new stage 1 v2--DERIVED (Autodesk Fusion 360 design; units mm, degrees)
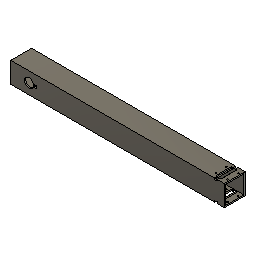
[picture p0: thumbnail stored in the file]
parameter "d495" = 0
parameter "d496" = 0
parameter "d497" = 0
parameter "d498" = 0
sketch "Sketch1" plane through (0, 0, 0) normal (1, 0, 0) x axis (0, 0, -1)
  line L1 (50.8, 0) -> (0, 0)
  line L2 (50.8, 50.8) -> (50.8, 0)
  line L3 (0, 50.8) -> (50.8, 50.8)
  line L4 (0, 0) -> (0, 50.8)
  line L5 (47.5234, 3.2766) -> (3.2766, 3.2766)
  line L6 (47.5234, 47.5234) -> (47.5234, 3.2766)
  line L7 (3.2766, 47.5234) -> (47.5234, 47.5234)
  line L8 (3.2766, 3.2766) -> (3.2766, 47.5234)
  point P1 (0, 0)
  point P2 (0, 0)
  point P3 (50.8, 0)
  point P5 (0, 50.8)
  horizontal L1
  vertical L2
  horizontal L3
  vertical L4
  coincident P1 P2
  dimension "d1_1" distance P2 P3 = 50.8
  dimension "d2_1" distance P2 P5 = 50.8
  dimension "d3_1" = -3.2766
  dimension "d158" OffsetX = 0
  dimension "d159" OffsetY = 0
  dimension "d160" OffsetZ = 0
  dimension "d161" AngleZ = 0
  dimension "d215" OffsetX = 0
  dimension "d216" OffsetY = 0
  dimension "d217" OffsetZ = 0
  dimension "d218" AngleZ = 0
  dimension "d223" OffsetX = 0
  dimension "d224" OffsetY = 0
  dimension "d225" OffsetZ = 0
  dimension "d226" AngleZ = 0
  dimension "d231" OffsetX = 0
  dimension "d232" OffsetY = 0
  dimension "d233" OffsetZ = 0
  dimension "d234" AngleZ = 0
  dimension "d239" OffsetX = 0
  dimension "d240" OffsetY = 0
  dimension "d241" OffsetZ = 0
  dimension "d242" AngleZ = 0
  dimension "d339" OffsetX = 0
  dimension "d340" OffsetY = 0
  dimension "d341" OffsetZ = 0
  dimension "d342" AngleZ = 0
  dimension "d347" OffsetX = 0
  dimension "d348" OffsetY = 0
  dimension "d349" OffsetZ = 0
  dimension "d350" AngleZ = 0
  dimension "d355" OffsetX = 0
  dimension "d356" OffsetY = 0
  dimension "d357" OffsetZ = 0
  dimension "d358" AngleZ = 0
  dimension "d363" OffsetX = 0
  dimension "d364" OffsetY = 0
  dimension "d365" OffsetZ = 0
  dimension "d366" AngleZ = 0
  dimension "d376" OffsetX = 0
  dimension "d377" OffsetY = 0
  dimension "d378" OffsetZ = 0
  dimension "d379" AngleZ = 0
  dimension "d384" OffsetX = 0
  dimension "d385" OffsetY = 0
  dimension "d386" OffsetZ = 0
  dimension "d387" AngleZ = 0
  dimension "d392" OffsetX = 0
  dimension "d393" OffsetY = 0
  dimension "d394" OffsetZ = 0
  dimension "d395" AngleZ = 0
  dimension "d479" OffsetX = 0
  dimension "d480" OffsetY = 0
  dimension "d481" OffsetZ = 0
  dimension "d482" AngleZ = 0
  dimension "d487" OffsetX = 0
  dimension "d488" OffsetY = 0
  dimension "d489" OffsetZ = 0
  dimension "d490" AngleZ = 0
extrude "Extrude1" new body sketch "Sketch1" along a picked direction blind 520.7 named "d4_1"
hole "Hole2" HoleDepth 101.6 HoleDiameter 22.225 TipAngle 118 RefDim1 44.45 (= "1 in + ( 3 / 4 ) * 1 in") RefDim2 25.4
sketch "Sketch2" plane through (0, 0, 0) normal (0, 0, 1) x axis (1, 0, 0)
  line L1 (0, 50.8) -> (520.7, 50.8)
  line L2 (0, 0) -> (0, 50.8)
  line L3 (520.7, 0) -> (0, 0)
  line L4 (496.7478, 47.498) -> (503.3518, 47.498)
  line L5 (496.7478, 54.102) -> (496.7478, 47.498)
  line L6 (503.3518, 54.102) -> (496.7478, 54.102)
  line L7 (503.3518, 47.498) -> (503.3518, 54.102)
  line L8 (496.7478, 54.102) -> (503.3518, 47.498)
  line L9 (503.3518, 54.102) -> (496.7478, 47.498)
  line L10 (496.7478, 3.302) -> (503.3518, 3.302)
  line L11 (496.7478, -3.302) -> (496.7478, 3.302)
  line L12 (503.3518, -3.302) -> (496.7478, -3.302)
  line L13 (503.3518, 3.302) -> (503.3518, -3.302)
  line L14 (496.7478, -3.302) -> (503.3518, 3.302)
  line L15 (503.3518, -3.302) -> (496.7478, 3.302)
  line L16 (520.7, 50.8) -> (520.7, 0)
  line L17 (520.7, 50.8) -> (520.7, 0)
  circle C1 centre (44.45, 25.4) radius 11.1125
  circle C2 centre (500.0498, 50.8) radius 3.302
  circle C3 centre (500.0498, 0) radius 3.302
  point P7 (500.0498, 50.8)
  point P8 (500.0498, 0)
  point P13 (500.0498, 50.8)
  point P18 (500.0498, 0)
  point P10 (496.7478, 47.498)
  point P11 (496.7478, 54.102)
  point P12 (503.3518, 54.102)
  point P16 (496.7478, -3.302)
  point P17 (503.3518, -3.302)
  point P15 (496.7478, 3.302)
  coincident L1 P7
  coincident L3 P8
  perpendicular L4 L5
  parallel L4 L6
  parallel L5 L7
  horizontal L4
  coincident L8 P13
  coincident L9 P13
  coincident P7 P13
  perpendicular L10 L11
  parallel L10 L12
  parallel L11 L13
  horizontal L10
  coincident L14 P18
  coincident L15 P18
  coincident P8 P18
  dimension "d412" diameter C2 = 6.604
  dimension "d413" diameter C3 = 6.604
  dimension "d428" distance P10 P11 = 6.604
  dimension "d429" distance P11 P12 = 6.604
  dimension "d430" distance P16 P17 = 6.604
  dimension "d431" distance P15 P16 = 6.604
  dimension "d540" distance L13 L17 = 17.3482
  dimension "d541" distance L7 L17 = 17.3482
extrude "Extrude3" cut sketch "Sketch2" profile of L1 L3 C2 C3 L4 L5 L7 L10 L11 L13 along a picked direction blind -50.8
sketch "Sketch3" plane through (0, 0, 0) normal (0, -1, 0) x axis (1, 0, 0)
  line L1 (520.7, -50.8) -> (503.3518, -50.8)
  line L2 (503.3518, 0) -> (520.7, 0)
  line L3 (493.1918, -6.35) -> (506.9078, -6.35)
  line L4 (493.1918, -19.05) -> (493.1918, -6.35)
  line L5 (506.9078, -19.05) -> (493.1918, -19.05)
  line L6 (506.9078, -6.35) -> (506.9078, -19.05)
  line L7 (493.1918, -19.05) -> (506.9078, -19.05)
  line L8 (493.1918, -44.45) -> (493.1918, -19.05)
  line L9 (506.9078, -44.45) -> (493.1918, -44.45)
  line L10 (506.9078, -19.05) -> (506.9078, -44.45)
  line L11 (503.3518, -50.8) -> (503.3518, 0)
  line L12 (496.7478, 0) -> (496.7478, -50.8)
  line L13 (520.7, 0) -> (520.7, -50.8)
  line L14 (496.7478, 0) -> (496.7478, -50.8)
  line L15 (0, 0) -> (496.7478, 0)
  line L16 (0, -50.8) -> (0, 0)
  line L17 (496.7478, -50.8) -> (0, -50.8)
  point P6 (506.9078, -6.35)
  point P9 (506.9078, -19.05)
  point P7 (493.1918, -6.35)
  point P10 (506.9078, -19.05)
  point P11 (493.1918, -19.05)
  point P13 (506.9078, -44.45)
  horizontal L3
  vertical L4
  horizontal L5
  vertical L6
  horizontal L7
  vertical L8
  horizontal L9
  vertical L10
  dimension "d418" distance P6 P9 = 12.7
  dimension "d419" distance P6 P7 = 13.716
  dimension "d420" distance P10 P11 = 13.716
  dimension "d421" distance P10 P13 = 25.4
  dimension "d422" distance L1 L9 = 6.35
  dimension "d423" distance L2 L3 = 6.35
  dimension "d432" distance L4 L12 = 3.556
  dimension "d433" distance L8 L12 = 3.556
extrude "Extrude4" cut sketch "Sketch3" profile of L3 L4 L5 L6 L7 L8 L9 L10 L11 L12 against normal blind 3.175
extrude "Extrude5" sketch "Sketch3" profile of L3 L4 L5 L6 L7 L8 L9 L10 L11 L12 blind 3.175
fillet "Fillet1" radius 1.5875 1.5875
sketch "Sketch4" plane through (0, 50.8, 0) normal (0, 1, 0) x axis (-1, 0, 0)
  line L1 (-469.3793, -6.35) -> (-469.7603, -6.35)
  line L2 (-467.7918, -42.8625) -> (-467.7918, -7.9375)
  line L3 (-469.7603, -44.45) -> (-469.3793, -44.45)
  line L4 (-471.3478, -50.8) -> (-471.3478, -46.0375)
  line L5 (0, -50.8) -> (-471.3478, -50.8)
  line L6 (0, 0) -> (0, -50.8)
  line L7 (-471.3478, 0) -> (0, 0)
  line L8 (-471.3478, -4.7625) -> (-471.3478, 0)
  line L9 (-520.7, -50.8) -> (-477.9518, -50.8)
  line L10 (-503.3518, 0) -> (-503.3518, -4.7625)
  line L11 (-520.7, 0) -> (-503.3518, 0)
  line L12 (-520.7, -50.8) -> (-520.7, 0)
  line L13 (-503.3518, -50.8) -> (-520.7, -50.8)
  line L14 (-503.3518, -46.0375) -> (-503.3518, -50.8)
  line L15 (-505.3203, -44.45) -> (-504.9393, -44.45)
  line L16 (-506.9078, -7.9375) -> (-506.9078, -42.8625)
  line L17 (-504.9393, -6.35) -> (-505.3203, -6.35)
  arc A1 centre (-469.7603, -4.7625) radius 1.5875 clockwise from (-469.7603, -6.35) to (-471.3478, -4.7625)
  arc A2 centre (-469.3793, -7.9375) radius 1.5875 clockwise from (-469.3793, -6.35) to (-467.7918, -7.9375)
  arc A3 centre (-469.7603, -46.0375) radius 1.5875 clockwise from (-471.3478, -46.0375) to (-469.7603, -44.45)
  circle C1 centre (-515.9248, -38.1) radius 2.5527
  circle C2 centre (-487.3498, -38.1) radius 2.5527
  circle C3 centre (-515.9248, -12.7) radius 2.5527
  circle C4 centre (-487.3498, -12.7) radius 2.5527
  arc A4 centre (-469.3793, -42.8625) radius 1.5875 clockwise from (-467.7918, -42.8625) to (-469.3793, -44.45)
  arc A5 centre (-504.9393, -4.7625) radius 1.5875 clockwise from (-503.3518, -4.7625) to (-504.9393, -6.35)
  arc A6 centre (-504.9393, -46.0375) radius 1.5875 clockwise from (-504.9393, -44.45) to (-503.3518, -46.0375)
  arc A7 centre (-505.3203, -42.8625) radius 1.5875 clockwise from (-505.3203, -44.45) to (-506.9078, -42.8625)
  arc A8 centre (-505.3203, -7.9375) radius 1.5875 clockwise from (-506.9078, -7.9375) to (-505.3203, -6.35)
  point P17 (-515.9248, -38.1)
  dimension "d441" diameter C1 = 5.1054
  dimension "d443" distance P17 L9 = 12.7
  dimension "d539" distance P17 L12 = 4.7752
  dimension "d446" R-Pattern1-uDistance = 28.575
  dimension "d447" R-Pattern1-vDistance = 25.4
hole "Hole3" HoleDepth 50.8 HoleDiameter 3.429 TipAngle 118
sketch "Sketch5" plane through (0, 0, 0) normal (0, 0, 1) x axis (1, 0, 0)
  line L1 (503.3518, 47.498) -> (503.3518, 50.8)
  line L2 (496.7478, 47.498) -> (503.3518, 47.498)
  line L3 (496.7478, 50.8) -> (496.7478, 47.498)
  line L4 (0, 50.8) -> (496.7478, 50.8)
  line L5 (0, 0) -> (0, 50.8)
  line L6 (496.7478, 0) -> (0, 0)
  line L7 (496.7478, 3.302) -> (496.7478, 0)
  line L8 (503.3518, 3.302) -> (496.7478, 3.302)
  line L9 (503.3518, 0) -> (503.3518, 3.302)
  line L10 (520.7, 0) -> (503.3518, 0)
  line L11 (520.7, 50.8) -> (520.7, 0)
  line L12 (503.3518, 50.8) -> (520.7, 50.8)
  circle C1 centre (44.45, 25.4) radius 11.1125
  circle C2 centre (60.325, 25.4) radius 3.3782
  point P14 (44.45, 25.4)
  point P15 (60.325, 25.4)
  dimension "d542" diameter C2 = 6.7564
  dimension "d543" distance P14 P15 = 15.875
  dimension "d544" distance L4 P15 = 25.4
hole "Hole4" HoleDepth 38.1 HoleDiameter 6.7564 TipAngle 118
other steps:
thread "Thread1"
